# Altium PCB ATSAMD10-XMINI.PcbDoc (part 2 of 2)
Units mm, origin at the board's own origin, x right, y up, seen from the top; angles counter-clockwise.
Board outline 60 x 75 mm, 4 copper layers (Top Layer, GND, Power Plane, Bottom Layer), stack 1.578 mm thick; 62 components, 78 nets, 549 pads, 117 vias.
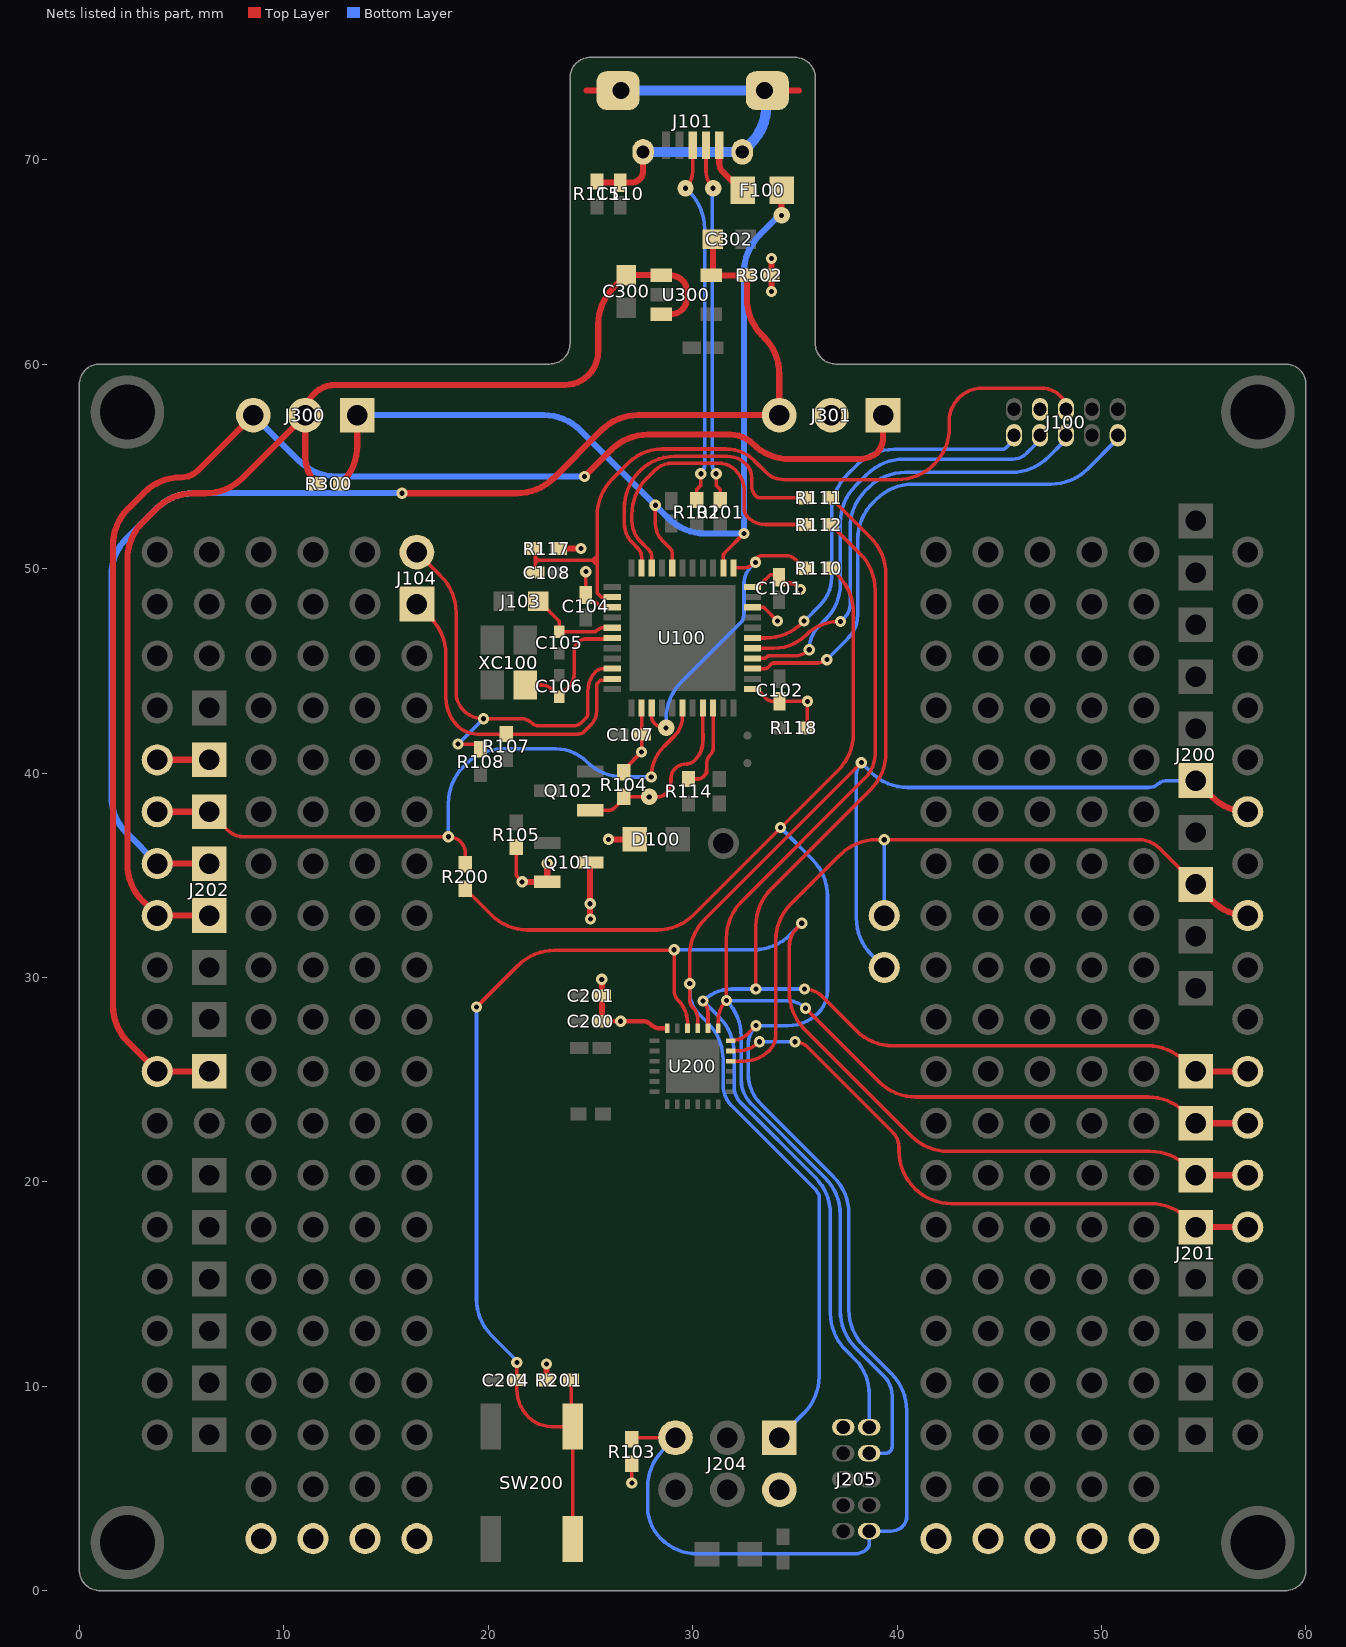
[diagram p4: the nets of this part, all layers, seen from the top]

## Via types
v1: diameter 0.55, hole 0.25, Top Layer to Bottom Layer, 102 vias
v2: diameter 0.55/0.55/0.8 (per signal layer), hole 0.25, Top Layer to Bottom Layer, tented top, 13 vias
v3: diameter 0.55, hole 0.25, Top Layer to Bottom Layer, tented top, 1 vias
v4: diameter 0.8, hole 0.4, Top Layer to Bottom Layer, 1 vias

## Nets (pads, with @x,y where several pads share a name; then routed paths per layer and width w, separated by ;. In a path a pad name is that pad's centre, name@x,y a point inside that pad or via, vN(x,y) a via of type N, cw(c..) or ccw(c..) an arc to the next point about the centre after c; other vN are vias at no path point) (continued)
PA23: J200.3@54.61,34.553 pad.12@57.15,33.029 pad.@39.37,33.029 U200.16 | length 38.1
  Top Layer w0.175: U200.16@31.86,25.909 32.487,25.909 ccw(c32.487,27.706) 33.757,26.435 ccw(c33.019,27.173) 34.063,27.173 34.063,31.806 cw(c36.603,31.806) 34.807,33.602 37.029,35.824 cw(c38.825,34.028) 37.239,36.013 cw(c38.997,34.256) 38.997,36.741 v1(39.37,36.741) 39.801,36.741 51.812,36.741 cw(c51.812,35.269) 52.853,36.31 J200.3@54.61,34.553
  Top Layer w0.3: J200.3@54.61,34.553 55.416,33.747 ccw(c57.15,35.481) pad.12@57.15,33.029
  Bottom Layer w0.175: pad.@39.37,33.029 v1(39.37,36.741)
PA24: J200.5@54.61,39.633 J204.1@34.24,7.489 pad.12@57.15,38.109 pad.@39.37,30.489 U200.21 | length 72.2
  Top Layer w0.175: U200.21@30.25,27.519 30.25,27.947 ccw(c29.391,27.947) 29.998,28.554 cw(c30.346,28.902) 29.854,28.902 v1(29.854,29.698) 29.854,31.061 cw(c32.394,31.061) 30.598,32.857 v1(38.25,40.509)
  Top Layer w0.3: J200.5@54.61,39.633 55.416,38.827 ccw(c57.15,40.561) pad.12@57.15,38.109
  Bottom Layer w0.175: v1(29.854,29.698) 29.854,29.3 ccw(c31.379,29.3) 30.301,28.222 30.742,27.781 cw(c28.946,25.985) 31.414,26.585 cw(c28.946,25.985) 31.486,25.985 31.486,24.741 ccw(c32.913,24.741) 31.904,23.732 35.975,19.66 cw(c35.349,19.034) 36.188,19.318 36.188,10.489 cw(c33.648,10.489) 35.444,8.693 J204.1@34.24,7.489 ; pad.@39.37,30.489 38.748,31.111 cw(c40.544,32.907) 38.004,32.907 38.004,39.914 cw(c38.845,39.914) v1(38.25,40.509) 38.719,40.039 ccw(c40.515,41.835) 40.515,39.295 52.288,39.295 ccw(c52.288,40.12) 52.658,39.383 cw(c53.267,38.764) 52.871,39.537 cw(c53.267,38.764) 53.267,39.633 J200.5@54.61,39.633
PA25: C204.2 J201.6@54.61,20.329 pad.12@57.15,20.329 R201.1 SW200.3 SW200.4 U200.22 | length 84.3
  Top Layer w0.175: v1(19.425,28.554) 21.459,30.587 cw(c23.255,28.791) 23.255,31.331 29.031,31.331 ccw(c29.031,31.418) v1(29.093,31.357) 29.093,29.352 ccw(c29.752,29.352) 29.286,28.886 cw(c28.166,27.766) 29.75,27.766 U200.22@29.75,27.519 ; v1(21.4,11.166) C204.2@21.4,10.309 21.4,9.857 ccw(c23.311,9.857) 21.96,8.506 ccw(c23.099,9.645) 23.099,8.034 SW200.4@24.125,8.034 ; SW200.4@23.795,8.975 23.795,8.829 ccw(c24.921,8.829) SW200.4@24.125,8.034 ; R201.1@24.05,10.309 24.05,8.215 ccw(c24.306,8.215) SW200.4@24.125,8.034 ; SW200.3@24.125,2.534 SW200.4@24.125,8.034 ; v1(35.336,32.655) 35.1,32.419 ccw(c36.004,31.515) 34.725,31.515 34.725,29.271 ccw(c37.265,29.271) 35.469,27.475 40.704,22.24 ccw(c42.5,24.036) 42.5,21.496 52.391,21.496 cw(c52.391,18.956) 54.187,20.752 J201.6@54.61,20.329 cw(c54.61,20.93) 54.185,20.505 J201.6@53.938,20.752
  Top Layer w0.3: J201.6@54.61,20.329 pad.12@57.15,20.329
  Bottom Layer w0.175: v1(19.425,28.554) 19.425,14.277 ccw(c21.965,14.277) 20.169,12.481 21.424,11.225 cw(c21.341,11.225) v1(21.4,11.166) ; v1(29.093,31.357) 32.986,31.357 ccw(c32.986,33.897) 34.782,32.101 v1(35.336,32.655)
PA27: J201.5@54.61,17.789 pad.12@57.15,17.789 U200.17 | length 29.8
  Top Layer w0.175: U200.17@31.86,26.409 32.181,26.409 ccw(c32.181,27.943) 32.718,26.506 ccw(c32.181,27.943) v1(33.266,26.858) ; v1(35,26.859) cw(c35,26.005) 35.603,26.609 39.781,22.431 cw(c39.027,21.678) 40.093,21.678 40.093,21.506 ccw(c42.633,21.506) 40.837,19.71 40.867,19.68 ccw(c42.663,21.476) 42.663,18.936 52.41,18.936 cw(c52.41,16.396) 54.206,18.192 J201.5@54.61,17.789
  Top Layer w0.3: J201.5@54.61,17.789 pad.12@57.15,17.789
  Bottom Layer w0.175: v1(33.266,26.858) v1@35.049,26.858 ; v1(35,26.859) v1@35.049,26.859
PA28: J204.5@29.16,7.489 J205.10@38.635,2.919 R103.1 R110.2 R200.1 U200.18 | length 95.4
  Top Layer w0.175: R200.1@18.875,34.334 20.14,33.069 ccw(c21.936,34.865) 21.936,32.325 28.255,32.325 ccw(c28.255,34.865) 30.051,33.069 37.12,40.138 ccw(c35.324,41.934) 37.864,41.934 37.864,47.858 ccw(c35.324,47.858) 37.12,49.654 R110.2@36.758,50.016 ; R103.1@27.025,7.409 cw(c27.218,7.216) 27.218,7.489 J204.5@29.16,7.489 ; U200.18@31.86,26.909 ccw(c31.86,28.131) 32.725,27.267 v1(33.101,27.643)
  Bottom Layer w0.175: J204.5@29.16,7.489 28.539,6.868 ccw(c30.335,5.072) 27.795,5.072 27.795,4.101 ccw(c29.983,4.101) 28.436,2.554 ccw(c30.232,4.35) 30.232,1.81 37.925,1.81 ccw(c37.925,2.689) 38.547,2.068 ccw(c38.334,2.281) 38.635,2.281 J205.10@38.635,2.919 39.712,2.919 ccw(c39.712,3.704) 40.267,3.149 ccw(c39.78,3.636) 40.469,3.636 40.469,8.814 ccw(c37.929,8.814) 39.725,10.61 38.388,11.947 cw(c40.184,13.743) 37.644,13.743 37.644,18.443 ccw(c35.104,18.443) 36.9,20.239 33.325,23.814 cw(c34.791,25.28) 32.718,25.28 32.718,26.718 cw(c34.026,26.718) v1(33.101,27.643) 34.653,27.643 ccw(c34.653,29.738) 36.135,28.257 ccw(c35.027,29.365) 36.594,29.365 36.594,33.987 ccw(c34.054,33.987) 35.85,35.783 v1(34.295,37.338)
PA30: J201.7@54.61,22.869 J205.4@38.635,6.729 pad.12@57.15,22.869 R112.2 U200.19 | length 82.5
  Top Layer w0.175: U200.19@31.25,27.519 31.25,27.9 cw(c32.623,27.9) v1(31.652,28.871) 31.652,31.92 cw(c34.192,31.92) 32.396,33.716 38.444,39.765 ccw(c37.291,40.918) 38.922,40.918 38.922,48.942 ccw(c36.382,48.942) 38.178,50.739 R112.2@36.758,52.159 ; v1(35.516,28.498) 39.115,24.898 ccw(c40.911,26.694) 40.911,24.154 52.272,24.154 cw(c52.272,21.614) 54.068,23.41 J201.7@54.61,22.869
  Top Layer w0.3: J201.7@54.61,22.869 pad.12@57.15,22.869
  Bottom Layer w0.175: v1(35.516,28.498) ccw(c34.615,27.597) 34.615,28.871 v1(31.652,28.871) cw(c29.915,27.133) 32.372,27.133 32.372,25.03 ccw(c34.116,25.03) 32.883,23.797 36.476,20.203 cw(c34.68,18.407) 37.22,18.407 37.22,13.69 ccw(c39.76,13.69) 37.964,11.894 39.352,10.506 cw(c38.385,9.539) 39.753,9.539 39.753,7.044 cw(c39.438,7.044) 39.438,6.729 J205.4@38.635,6.729 ccw(c38.922,6.729) J205.4@38.922,6.441
PA31: J201.8@54.61,25.409 J205.2@38.635,7.999 pad.12@57.15,25.409 R111.2 U200.20 | length 80.7
  Top Layer w0.175: v1(30.51,28.852) cw(c29.932,28.273) 30.75,28.273 U200.20@30.75,27.519 ; v1(33.089,29.438) 33.089,32.522 cw(c35.629,32.522) 33.833,34.318 38.709,39.195 ccw(c36.913,40.991) 39.453,40.991 39.453,49.719 ccw(c36.913,49.719) 38.709,51.515 R111.2@36.758,53.466 ; v1(35.476,29.438) cw(c35.476,28.258) 36.31,29.093 37.997,27.405 ccw(c39.794,29.201) 39.794,26.661 52.248,26.661 cw(c52.248,24.121) 54.045,25.917 J201.8@54.553,25.409
  Top Layer w0.3: J201.8@54.61,25.409 pad.12@57.15,25.409
  Bottom Layer w0.175: v1(35.476,29.438) v1(33.089,29.438) 31.925,29.438 ccw(c31.925,27.437) v1(30.51,28.852) 31.284,28.078 cw(c29.488,26.282) 32.028,26.282 32.028,24.663 ccw(c33.167,24.663) 32.362,23.858 35.995,20.224 cw(c34.199,18.428) 36.739,18.428 36.739,13.574 ccw(c39.279,13.574) 37.27,12.021 ccw(c39.279,13.574) 37.483,11.778 38.105,11.157 cw(c36.095,9.604) 38.635,9.604 J205.2@38.635,7.999
PD2_UART_RXD1: J104.2@16.51,50.809 R108.1 U100.20 | length 21.1
  Top Layer w0.175: J104.2@16.51,50.809 17.681,49.638 cw(c15.885,47.842) 18.425,47.842 18.425,43.964 ccw(c19.705,43.964) 18.8,43.059 ccw(c19.766,44.024) v1(19.766,42.659) 21.607,42.659 cw(c21.607,41.89) 22.15,42.434 ccw(c22.452,42.735) 22.452,42.309 24.153,42.309 ccw(c24.153,42.906) 24.575,42.484 24.769,42.678 ccw(c24.513,42.934) 24.875,42.934 24.875,44.006 cw(c26.248,44.006) 25.277,44.977 cw(c25.595,44.66) 25.595,45.109 U100.20@26.075,45.109 ; v1(18.525,41.418) 19.366,41.418 R108.1@19.625,41.159
  Bottom Layer w0.175: v1(18.525,41.418) v1(19.766,42.659)
PD3_UART_TXD1: J104.1@16.51,48.269 R107.1 U100.21 | length 16.3
  Top Layer w0.175: J104.1@16.51,48.269 17.181,47.598 cw(c15.385,45.802) 17.925,45.802 17.925,43.697 ccw(c19.888,43.697) 18.5,42.309 ccw(c19.466,43.274) 19.466,41.909 R107.1@20.875,41.909 24.398,41.909 ccw(c24.398,42.335) 24.7,42.034 25.017,42.351 ; 25.017,42.351 ccw(c24.334,43.034) 25.3,43.034 25.3,44.26 cw(c25.533,44.26) 25.368,44.425 25.477,44.534 26,44.534 U100.21@26.075,44.609
POWER_ENABLE: Q102.1 R104.1 U100.30 | length 10.4
  Top Layer w0.175: Q102.1@24.985,38.179 25.902,38.179 ccw(c25.902,38.547) 25.962,38.184 ccw(c25.902,38.547) 26.162,38.286 26.565,38.69 ccw(c26.422,38.834) R104.1@26.625,38.834 v2(27.878,38.834) 28.306,38.834 ccw(c28.306,39.331) 28.658,38.979 ccw(c27.977,39.66) 28.94,39.66 28.94,39.764 cw(c29.566,39.764) 29.123,40.206 cw(c29.701,39.629) 29.701,40.445 ccw(c29.701,40.978) 30.077,40.601 ccw(c29.043,41.635) 30.178,40.713 ; U100.30@30.5,43.184 30.5,41.51 ; 30.505,41.919 30.505,41.635 cw(c29.043,41.635) 30.5,41.51 ; 30.178,40.713 ccw(c29.043,41.635) 30.5,41.51 ; 30.178,40.713 ccw(c29.4,41.491) 30.5,41.491 30.5,41.51
RESET_SENSE: J202.3@6.35,38.109 pad.0@3.81,38.109 R200.2 U100.28 | length 33.9
  Top Layer w0.175: J202.3@6.35,38.109 7.239,37.22 ccw(c8.05,38.03) 8.05,36.884 v1(18.046,36.884) cw(c18.046,36.03) 18.65,36.634 cw(c18.107,36.09) 18.875,36.09 R200.2@18.875,35.534 ; v1(27.975,39.809) cw(c30.087,39.809) 28.594,41.302 29.108,41.817 ccw(c28.163,42.762) U100.28@29.5,42.762 ; 29.5,42.736 U100.28@29.5,42.762 ; U100.28@29.5,43.184 U100.28@29.5,42.762
  Top Layer w0.3: pad.0@3.81,38.109 J202.3@6.35,38.109
  Bottom Layer w0.175: v1(18.046,36.884) 18.046,38.52 cw(c20.586,38.52) 18.79,40.316 18.957,40.482 cw(c20.656,38.784) 20.656,41.186 23.289,41.186 cw(c23.289,39.023) 24.819,40.553 ccw(c26.615,42.349) 26.615,39.809 v1(27.975,39.809)
S\R\S\T\: C108.2 J100.6@48.26,57.794 R117.1 U100.13 | length 38.3
  Top Layer w0.175: R117.1@22.25,50.984 cw(c22.129,50.863) 22.3,50.863 22.3,50.409 ; 22.298,50.262 22.3,50.264 ; C108.2@22.3,49.809 22.3,50.264 ; 22.306,50.562 22.459,50.409 ; 22.562,50.409 22.459,50.409 ; 25.2,50.409 25.097,50.409 ; U100.13@26.075,48.609 25.525,48.609 25.325,48.809 25.325,50.181 ; J100.6@48.26,57.794 ccw(c47.343,57.794) 47.991,58.442 ccw(c47.047,57.498) 47.047,58.834 44.175,58.834 ccw(c44.175,57.209) 42.631,57.714 ccw(c44.175,57.209) 42.559,57.383 42.559,56.906 cw(c40.019,56.906) 41.815,55.11 41.802,55.097 cw(c40.006,56.893) 40.006,54.353 34.464,54.353 cw(c34.464,55.618) 33.569,54.723 33.002,55.291 ccw(c31.65,53.939) 31.65,55.851 28.499,55.851 ccw(c28.499,53.525) 26.854,55.17 26.069,54.384 ccw(c27.865,52.588) 25.325,52.588 25.325,50.637 ; 22.3,50.264 22.444,50.409 ; 22.3,50.264 22.3,50.409 ; 22.3,50.409 22.444,50.409 ; 22.444,50.409 22.459,50.409 ; 22.459,50.409 25.097,50.409 ; 25.097,50.409 25.325,50.637 ; 25.097,50.409 25.325,50.181 ; 25.325,50.181 25.325,50.637
SHIELD: C110.2 J101.6@33.512,73.384 J101.7@26.488,73.384 J101.8@32.425,70.384 J101.9@27.575,70.384 R115.1 | length 23.8
  Top Layer w0.3: 24.819,73.384 J101.7@26.4,73.384 ; R115.1@25.315,68.935 ccw(c25.436,69.055) 25.436,68.885 C110.2@26.458,68.885 27.008,68.885 ccw(c27.008,69.454) 27.411,69.051 ccw(c27.015,69.448) 27.575,69.448 J101.9@27.575,70.384 ; J101.7@26.4,72.636 J101.7@26.4,73.384 ; J101.7@26.488,73.384 J101.7@26.4,73.384 ; J101.6@33.512,73.384 J101.6@33.6,73.384 ; J101.6@33.6,72.594 J101.6@33.6,73.384 ; 35.193,73.384 J101.6@33.6,73.384
  Bottom Layer w0.5: J101.7@26.4,73.384 J101.7@26.488,73.384 J101.6@33.512,73.384 33.6,73.384 33.6,72.611 cw(c31.06,72.611) 32.856,70.815 J101.8@32.425,70.384 J101.9@27.575,70.384
STATUS_LED: R114.2 U100.31 | length 4.6
  Top Layer w0.175: R114.2@29.8,39.709 30.26,39.709 ccw(c30.26,40.056) 30.505,39.81 30.683,39.988 30.683,40.437 cw(c31.377,40.437) 30.886,40.928 ccw(c30.612,41.202) 31,41.202 U100.31@31,43.184 ; 30.54,39.845 ccw(c30.193,40.191) 30.683,40.191
SWCLK: R112.1 U100.9 | length 15
  Top Layer w0.175: U100.9@28,50.034 28,50.535 ccw(c27.423,50.535) 27.831,50.943 27.446,51.328 cw(c28.467,52.349) 27.023,52.349 27.023,52.631 cw(c29.563,52.631) 27.767,54.427 28.141,54.801 cw(c29,53.943) 29,55.157 31.267,55.157 cw(c31.267,53.982) 32.097,54.813 cw(c31.06,53.775) 32.527,53.775 32.527,52.898 ccw(c33.049,52.898) 32.68,52.528 ccw(c33.573,53.421) 33.573,52.159 R112.1@35.558,52.159
SWDIO: R111.1 U100.10 | length 14.9
  Top Layer w0.175: U100.10@27.5,50.034 27.5,50.569 ccw(c26.907,50.569) 27.326,50.988 27.053,51.261 cw(c28.018,52.225) 26.654,52.225 26.654,52.96 cw(c29.194,52.96) 27.398,54.756 27.442,54.8 cw(c29.119,53.122) 29.119,55.494 31.68,55.494 cw(c31.68,54.174) 32.614,55.108 cw(c31.956,54.45) 32.886,54.45 32.886,54.054 ccw(c33.607,54.054) 32.915,53.85 ccw(c33.607,54.054) 33.097,53.544 ccw(c33.284,53.731) 33.284,53.466 R111.1@35.558,53.466
TARGET_RESET: R110.1 U100.1 U100.25 | length 15.4
  Top Layer w0.175: U100.25@28,43.184 28,42.735 ccw(c28.427,42.735) 28.125,42.434 ccw(c28.668,42.977) 28.668,42.209 v2(28.7,42.209) ; U100.1@32,50.034 32.434,50.034 ccw(c32.434,50.947) v1@33.08,50.301 ; v1(33.075,50.309) cw(c33.4,50.309) 33.4,50.634 34.55,50.634 cw(c34.55,49.909) 35.275,49.909 R110.1@35.55,49.909
  Bottom Layer w0.175: v2(28.7,42.209) 28.7,42.657 cw(c31.24,42.657) 29.444,44.453 32.402,47.411 ; 32.402,47.411 ccw(c32.283,47.53) 32.452,47.53 ccw(c31.793,47.819) 32.512,47.819 32.512,49.285 cw(c33.625,49.285) 32.838,50.072 v1(33.075,50.309)
TCK: J100.1@45.72,56.524 U100.39 | length 19.5
  Top Layer w0.175: U100.39@32.925,46.609 33.573,46.609 ccw(c33.573,49.149) 35.369,47.353 v1(35.45,47.434)
  Bottom Layer w0.175: v1(35.45,47.434) 36.234,48.218 ccw(c34.869,49.584) 36.8,49.584 36.8,52.782 cw(c39.34,52.782) 37.544,54.578 38.056,55.09 cw(c39.852,53.294) 39.852,55.834 45.15,55.834 ccw(c45.15,56.075) 45.321,55.904 45.564,56.148 ccw(c45.189,56.524) J100.1@45.72,56.524
TDI: J100.9@50.8,56.524 U100.36 | length 25.4
  Top Layer w0.175: U100.36@32.925,45.109 33.525,45.109 ccw(c33.525,45.35) 33.696,45.179 33.85,45.334 ; 33.85,45.334 cw(c33.971,45.213) 33.971,45.384 36.128,45.384 ccw(c36.128,45.981) 36.55,45.559 v1(36.562,45.547)
  Bottom Layer w0.175: v1(36.562,45.547) 37.581,46.565 ccw(c36.387,47.759) 38.075,47.759 38.075,51.432 cw(c40.615,51.432) 38.819,53.228 38.981,53.39 cw(c40.777,51.594) 40.777,54.134 47.523,54.134 ccw(c47.523,56.674) 49.319,54.878 50.683,56.242 ccw(c50.402,56.524) J100.9@50.8,56.524
TDO: J100.3@46.99,56.524 U100.37 | length 21.6
  Top Layer w0.175: U100.37@32.925,45.609 33.444,45.609 ccw(c33.444,45.865) 33.625,45.684 cw(c33.746,45.563) 33.746,45.734 34.976,45.734 ccw(c34.976,46.758) v1(35.7,46.034)
  Bottom Layer w0.175: v1(35.7,46.034) cw(c37.33,46.034) 36.177,47.186 36.5,47.509 ccw(c34.75,49.259) 36.6,47.615 ccw(c34.75,49.259) 37.225,49.259 37.225,52.257 cw(c39.765,52.257) 37.969,54.053 38.531,54.615 cw(c40.327,52.819) 40.327,55.359 45.65,55.359 ccw(c45.65,56.324) 46.333,55.641 46.831,56.14 ccw(c46.447,56.524) J100.3@46.99,56.524
TMS: J100.5@48.26,56.524 U100.38 | length 22.2
  Top Layer w0.175: U100.38@32.925,46.109 33.981,46.109 ccw(c33.981,48.328) 35.55,46.759 cw(c37.119,45.189) 37.119,47.409 v1(37.236,47.409)
  Bottom Layer w0.175: v1(37.236,47.409) 37.427,47.599 ccw(c36.767,48.259) 37.7,48.259 37.7,52.007 cw(c40.24,52.007) 38.444,53.803 38.606,53.965 cw(c40.402,52.169) 40.402,54.709 45.598,54.709 ccw(c45.598,57.249) 47.394,55.453 48.115,56.174 ccw(c47.765,56.524) J100.5@48.26,56.524
USB_VBUS: F100.1 J101.1 | length 2.7
  Top Layer w0.3: J101.1@31.3,70.709 31.3,69.831 ccw(c31.897,69.831) 31.475,69.409 32.322,68.562 ccw(c32.45,68.69) F100.1@32.45,68.509
USBD_N: J101.2 R101.1 | length 17.6
  Top Layer w0.18: J101.2@30.65,70.709 30.65,69.454 ccw(c31.845,69.454) v2(31,68.609) ; v1(31.15,54.644) 31.15,54.071 31.35,53.871 R101.1@31.35,53.359
  Bottom Layer w0.18: v2(31,68.609) ccw(c31.084,68.524) 30.965,68.524 30.965,55.091 ccw(c31.597,55.091) v1(31.15,54.644) v1@31.15,54.693
USBD_P: J101.3 R102.1 | length 17.9
  Top Layer w0.18: v2(29.65,68.609) ccw(c28.805,69.454) 30,69.454 J101.3@30,70.709 ; R102.1@30.2,53.359 30.2,53.871 30.4,54.071 v1(30.4,54.644)
  Bottom Layer w0.18: v2(29.65,68.609) 29.841,68.418 cw(c28.045,66.622) 30.585,66.622 30.585,55.091 cw(c29.953,55.091) v1(30.4,54.644)
VCC_BOARD: C101.2 C102.1 C104.1 C107.2 D100.2 J100.4@46.99,57.794 J301.2@36.775,57.509 Q101.2 R104.2 R105.2 R117.2 R118.2 R302.2 U100.14 U100.24 U100.34 U100.42 U100.44 | length 22.6
  Top Layer w0.175: R105.2@21.375,36.384 21.375,35.054 ccw(c21.546,35.054) 21.425,34.934 21.644,34.715 cw(c21.607,34.679) v1(21.659,34.679) ; v1(24.775,49.853) C104.1@24.775,48.709 24.775,48.578 24.819,48.534 ccw(c24.819,48.665) 24.912,48.572 cw(c24.698,48.359) 25,48.359 25.275,48.359 25.525,48.109 U100.14@26.075,48.109 ; R104.2@26.625,40.034 cw(c26.916,40.034) 26.71,40.24 v1(27.5,41.029) C107.2@27.5,41.884 U100.24@27.5,43.184 ; U100.34@32.925,44.109 cw(c32.925,43.626) 33.266,43.967 33.575,43.659 ccw(c33.937,44.021) 33.937,43.509 C102.1@34.25,43.509 v1(35.615,43.509) 35.615,42.365 cw(c35.394,42.365) R118.2@35.55,42.209 ; U100.42@32.925,48.109 33.44,48.109 cw(c33.44,48.023) 33.5,48.084 v1(34.15,47.434) ; U100.44@32.925,49.109 ccw(c32.925,49.773) 33.394,49.303 33.8,49.709 C101.2@34.225,49.709
  Top Layer w0.2: 34.525,49.284 34.95,49.284 35.25,48.984 v1(35.275,48.984)
  Top Layer w0.3: v1(21.659,34.679) Q101.2@22.885,34.679 v1(22.885,35.572) ; R117.2@23.45,50.984 v1(24.54,50.984) ; v1(25.885,36.759) D100.2@27.175,36.759 ; v1(33.851,63.558) R302.2@33.851,64.357 v1(33.851,65.176)
  Bottom Layer w0.3: v1@21.55,34.634 cw(c21.659,34.525) v1(21.659,34.679) ; v1(22.885,35.572) cw(c22.936,35.572) v1@22.9,35.609
VCC_P3V3: C302.1 J202.4@6.35,35.569 J301.3@34.235,57.509 pad.0@3.81,35.569 R302.1 U300.5 | length 64.4
  Top Layer w0.3: pad.0@3.81,35.569 J202.4@6.35,35.569 ; v1(15.775,53.689) 21.404,53.689 ccw(c21.404,56.229) 23.2,54.433 25.532,56.765 cw(c27.328,54.969) 27.328,57.509 J301.3@34.235,57.509 34.235,59.528 ccw(c31.695,59.528) 33.491,61.325 33.395,61.42 cw(c35.191,63.217) 32.651,63.217 R302.1@32.651,64.357 cw(c32.623,64.385) 32.623,64.345 U300.5@30.918,64.345 ccw(c30.753,64.51) 30.986,64.51 C302.1@30.986,66.12
  Bottom Layer w0.3: pad.0@3.81,35.569 2.308,37.071 cw(c4.104,38.867) 1.564,38.867 1.564,49.683 cw(c4.104,49.683) 2.308,51.479 3.781,52.952 cw(c5.577,51.156) 5.577,53.696 v1@15.775,53.696
VCC_P5V0: C300.1 J202.5@6.35,33.029 J300.2@11.05,57.509 pad.0@3.81,33.029 R300.2 U300.1 U300.3 | length 61.6
  Top Layer w0.3: J202.5@6.35,33.029 pad.0@3.81,33.029 3.094,33.745 cw(c4.89,35.541) 2.35,35.541 2.35,50.468 cw(c4.89,50.468) 3.094,52.265 3.771,52.941 cw(c5.567,51.145) 5.567,53.685 6.174,53.685 ccw(c6.174,56.225) 7.97,54.429 J300.2@11.05,57.509 ; R300.2@11.6,54.159 cw(c12.928,55.486) 11.05,55.486 J300.2@11.05,57.509 ; U300.3@28.468,62.439 28.901,62.439 ccw(c28.901,63.298) 29.508,62.691 ccw(c29.062,63.137) 29.693,63.137 29.693,63.648 ccw(c29.062,63.648) 29.508,64.094 ccw(c28.901,63.487) 28.901,64.345 U300.1@28.468,64.345 ccw(c28.43,64.308) 28.43,64.361 C300.1@26.747,64.361 26.122,63.736 ccw(c27.918,61.94) 25.378,61.94 25.378,60.629 cw(c23.726,60.629) 24.894,59.461 cw(c23.754,60.602) 23.754,58.989 12.53,58.989 ccw(c12.53,57.509) J300.2@11.05,57.509
VCC_TARGET: C200.2 C201.2 J202.2@6.35,40.649 J204.2@34.24,4.949 J205.1@37.365,7.999 pad.0@3.81,40.649 pad.2@8.89,2.549 pad.3@11.43,2.549 pad.4@13.97,2.549 pad.5@16.51,2.549 pad.6@41.91,2.549 pad.7@44.45,2.549 pad.8@46.99,2.549 pad.9@49.53,2.549 pad.10@52.07,2.549 Q101.3 R103.2 R201.2 U200.24 | length 13.6
  Top Layer w0.175: v1(27.025,5.277) R103.2@27.025,6.209
  Top Layer w0.22: C200.2@25.566,27.861 v1(26.476,27.861) 27.578,27.861 cw(c27.578,27.344) 27.943,27.71 ccw(c28.405,28.171) 28.405,27.519 U200.24@28.75,27.519
  Top Layer w0.3: pad.0@3.81,40.649 J202.2@6.35,40.649 J202.2@5.669,39.967 ; R201.2@22.85,10.309 v1(22.85,11.099) ; Q101.3@24.985,35.629 v1(24.985,33.609) 24.985,32.874 v1(25,32.859) ; v1(25.55,29.909) 25.55,30.005 25.566,30.021 C201.2@25.566,29.111 C200.2@25.566,27.861
VCC_VBUS: F100.2 J300.1@13.59,57.509 R300.1 U100.2 U100.7 | length 47.6
  Top Layer w0.175: v1(28.175,53.101) 28.175,52.209 ccw(c29.382,52.209) 28.528,51.355 28.9,50.984 cw(c28.659,50.742) 29,50.742 U100.7@29,50.034 ; U100.2@31.5,50.034 31.5,50.638 cw(c31.671,50.638) 31.55,50.758 ; 31.55,50.759 v1(32.512,51.72)
  Top Layer w0.3: R300.1@12.8,54.159 12.846,54.205 ccw(c11.05,56.001) 13.59,56.001 J300.1@13.59,57.509 ; v2(34.35,67.284) F100.2@34.35,68.509
  Bottom Layer w0.3: J300.1@13.59,57.509 22.715,57.509 cw(c22.715,54.969) 24.511,56.765 v1(28.175,53.101) 28.812,52.464 ccw(c30.608,54.26) 30.608,51.72 v1(32.512,51.72) 32.512,64.502 cw(c35.052,64.502) 33.256,66.298 34.241,67.284 v2(34.35,67.284)
VCC_VIN: J202.8@6.35,25.409 J300.3@8.51,57.509 J301.1@39.315,57.509 pad.0@3.81,25.409 | length 73.6
  Top Layer w0.3: J202.8@6.35,25.409 pad.0@3.81,25.409 2.387,26.832 cw(c4.183,28.628) 1.643,28.628 1.643,51.145 cw(c4.183,51.145) 2.387,52.941 3.165,53.719 cw(c4.961,51.923) 4.961,54.463 ccw(c4.961,55.678) 5.82,54.819 J300.3@8.51,57.509 ; v1(24.714,54.512) 26.014,55.811 cw(c27.81,54.015) 27.81,56.555 31.852,56.555 cw(c31.852,55.006) 32.948,56.102 ccw(c34.744,57.898) 34.744,55.358 38.115,55.358 ccw(c38.115,56.868) 38.989,55.637 ccw(c38.204,56.423) 39.315,56.423 J301.1@39.315,57.509
  Bottom Layer w0.3: J300.3@8.51,57.509 10.763,55.255 ccw(c12.559,57.052) 12.559,54.512 v1(24.714,54.512)
XTAL1: C106.1 U100.17 XC100.1 | length 6.5
  Top Layer w0.175: XC100.1@21.9,44.309 22.598,44.309 cw(c22.598,43.58) 23.113,44.095 C106.1@23.475,43.734 23.923,44.181 ccw(c23.243,44.862) 23.928,44.186 ccw(c23.243,44.862) 24.205,44.862 24.205,46.043 cw(c24.616,46.043) 24.325,46.334 24.409,46.417 cw(c24.75,46.076) 24.75,46.559 25.954,46.559 ccw(c25.954,46.729) U100.17@26.075,46.609
XTAL2: C105.2 J103.2 U100.16 | length 4.6
  Top Layer w0.175: J103.2@22.45,48.409 cw(c22.45,48.288) 22.535,48.373 23.475,47.434 C105.2@23.475,46.909 25.144,46.909 ccw(c25.144,47.165) 25.325,46.984 cw(c25.627,46.682) 25.627,47.109 U100.16@26.075,47.109
pads on no net: J100.1@45.72,56.524 J100.2@45.72,57.794 J100.3@46.99,56.524 J100.4@46.99,57.794 J100.5@48.26,56.524 J100.6@48.26,57.794 J100.7@49.53,56.524 J100.8@49.53,57.794 J100.9@50.8,56.524 J100.10@50.8,57.794 J101.6@33.6,73.384 J101.7@26.4,73.384 J101.8@32.425,70.384 J101.9@27.575,70.384 J104.1@16.51,48.269 J104.2@16.51,50.809 J200.1@54.61,29.473 J200.2@54.61,32.013 J200.3@54.61,34.553 J200.4@54.61,37.093 J200.5@54.61,39.633 J200.6@54.61,42.173 J200.7@54.61,44.713 J200.8@54.61,47.253 J200.9@54.61,49.793 J200.10@54.61,52.333 J201.1@54.61,7.629 J201.2@54.61,10.169 J201.3@54.61,12.709 J201.4@54.61,15.249 J201.5@54.61,17.789 J201.6@54.61,20.329 J201.7@54.61,22.869 J201.8@54.61,25.409 J202.1@6.35,43.189 J202.2@6.35,40.649 J202.3@6.35,38.109 J202.4@6.35,35.569 J202.5@6.35,33.029 J202.6@6.35,30.489 J202.7@6.35,27.949 J202.8@6.35,25.409 J203.1@6.35,20.329 J203.2@6.35,17.789 J203.3@6.35,15.249 J203.4@6.35,12.709 J203.5@6.35,10.169 J203.6@6.35,7.629 J204.1@34.24,7.489 J204.2@34.24,4.949 J204.3@31.7,7.489 J204.4@31.7,4.949 J204.5@29.16,7.489 J204.6@29.16,4.949 J205.1@37.365,7.999 J205.2@38.635,7.999 J205.3@37.365,6.729 J205.4@38.635,6.729 J205.5@37.365,5.459 J205.6@38.635,5.459 J205.7@37.365,4.189 J205.8@38.635,4.189 J205.9@37.365,2.919 J205.10@38.635,2.919 J300.1@13.59,57.509 J300.2@11.05,57.509 J300.3@8.51,57.509 J301.1@39.315,57.509 J301.2@36.775,57.509 J301.3@34.235,57.509 QT200.1 U200.0
copper on no net: | length 238.8
  Top Layer w0.3: 3.81,22.869 6.35,22.869 ; 3.81,45.729 6.35,45.729 ; 3.81,48.269 6.35,48.269 ; 3.81,50.809 6.35,50.809 ; 8.89,7.629 11.43,7.629 ; 8.89,10.169 11.43,10.169 ; 8.89,12.709 11.43,12.709 ; 8.89,15.249 11.43,15.249 ; 8.89,17.789 11.43,17.789 ; 8.89,20.329 11.43,20.329 ; 8.89,22.869 11.43,22.869 ; 8.89,25.409 11.43,25.409 ; 8.89,27.949 11.43,27.949 ; 8.89,30.489 11.43,30.489 ; 8.89,33.029 11.43,33.029 ; 8.89,35.569 11.43,35.569 ; 8.89,38.109 11.43,38.109 ; 8.89,45.729 11.43,45.729 ; 8.89,48.269 11.43,48.269 13.97,48.269 ; 8.89,50.809 11.43,50.809 13.97,50.809 ; 13.97,7.629 16.51,7.629 ; 13.97,10.169 16.51,10.169 ; 13.97,12.709 16.51,12.709 ; 13.97,15.249 16.51,15.249 ; 13.97,17.789 16.51,17.789 ; 13.97,20.329 16.51,20.329 ; 13.97,22.869 16.51,22.869 ; 13.97,25.409 16.51,25.409 ; 13.97,27.949 16.51,27.949 ; 13.97,30.489 16.51,30.489 ; 13.97,33.029 16.51,33.029 ; 13.97,35.569 16.51,35.569 ; 13.97,38.109 16.51,38.109 ; 13.97,40.649 16.51,40.649 ; 13.97,43.189 16.51,43.189 ; 13.97,45.729 16.51,45.729 ; 41.91,7.629 44.45,7.629 ; 41.91,10.169 44.45,10.169 ; 41.91,12.709 44.45,12.709 ; 41.91,15.249 44.45,15.249 ; 41.91,17.789 44.45,17.789 ; 41.91,20.329 44.45,20.329 ; 41.91,22.869 44.45,22.869 ; 41.91,25.409 44.45,25.409 ; 41.91,27.949 44.45,27.949 ; 41.91,30.489 44.45,30.489 ; 41.91,33.029 44.45,33.029 ; 41.91,35.569 44.45,35.569 ; 41.91,38.109 44.45,38.109 ; 41.91,40.649 44.45,40.649 ; 41.91,43.189 44.45,43.189 ; 41.91,45.729 44.45,45.729 ; 41.91,48.269 44.45,48.269 ; 41.91,50.809 44.45,50.809 ; 46.99,7.629 52.07,7.629 ; 46.99,10.169 52.07,10.169 ; 46.99,12.709 52.07,12.709 ; 46.99,15.249 52.07,15.249 ; 46.99,17.789 52.07,17.789 ; 46.99,20.329 52.07,20.329 ; 46.99,22.869 52.07,22.869 ; 46.99,25.409 52.07,25.409 ; 46.99,27.949 52.07,27.949 ; 46.99,30.489 49.53,30.489 ; 46.99,33.029 49.53,33.029 ; 46.99,35.569 52.07,35.569 ; 46.99,38.109 52.07,38.109 ; 46.99,40.649 52.07,40.649 ; 46.99,43.189 52.07,43.189 ; 46.99,45.729 52.07,45.729 ; 46.99,48.269 52.07,48.269 ; 46.99,50.809 52.07,50.809 ; 8.89,40.649 11.43,40.649 8.89,40.649 ; 8.89,43.189 11.43,43.189 8.89,43.189

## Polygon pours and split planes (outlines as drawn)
no net on Top Overlay "GND Silk" (solid, pour order 16): 56,0.209 59.2,0.209 ccw(c59.2,0.709) 59.7,0.709 59.7,3.909 ccw(c59.2,3.909) 59.2,4.409 56,4.409 ccw(c56,3.909) 55.5,3.909 55.5,0.709 ccw(c56,0.709) 56,0.209
GND on Top Layer "Top-GND" (solid, remove dead copper, pour order 13): 0,0.009 0,69.207 60,69.207 60,0.009
SHIELD on Top Layer "USB Shield" (solid, remove dead copper, pour order 10): 25.25,69.709 24.92,69.709 cw(c24.92,70.38) 24.249,70.38 24.249,73.757 cw(c25.25,73.757) 25.25,74.759 34.75,74.759 cw(c34.75,73.759) 35.75,73.759 35.75,70.709 cw(c34.75,70.709) 34.75,69.709
GND on Bottom Layer "Bot-GND" (solid, remove dead copper, pour order 12): 0,0.009 0,69.207 60,69.207 60,0.009
SHIELD on GND "USB Shield" (solid, remove dead copper, pour order 9): 25.25,69.709 24.92,69.709 cw(c24.92,70.38) 24.249,70.38 24.249,73.757 cw(c25.25,73.757) 25.25,74.759 34.75,74.759 cw(c34.75,73.759) 35.75,73.759 35.75,70.709 cw(c34.75,70.709) 34.75,69.709
GND on GND "L2-GND" (solid, remove dead copper, pour order 11): 0,0.009 0,69.207 60,69.207 60,0.009
NetQT200_1 on GND "Touch" (solid, remove dead copper, pour order 8): 26.028,19.325 34.028,19.325 34.028,11.325 26.028,11.325
VCC_BOARD on Power Plane (split plane): 35.096,74.491 35.188,74.463 35.273,74.418 35.348,74.356 35.409,74.282 35.454,74.197 35.482,74.105 35.491,74.02 35.49,74.009 35.49,61.009 35.49,61.007 35.499,60.84 35.527,60.673 35.574,60.51 35.639,60.353 35.721,60.205 35.819,60.067 35.932,59.941 36.058,59.828 36.196,59.73 36.345,59.648 36.501,59.583 36.664,59.536 36.831,59.508 36.998,59.498 37,59.498 59,59.498 59.012,59.499 59.096,59.491 59.188,59.463 59.273,59.418 59.348,59.356 59.409,59.282 59.454,59.197 59.482,59.105 59.491,59.02 59.49,59.009 59.49,34.272 20.637,34.272 10.242,44.667 10.21,44.691 10.195,44.698 10.174,44.706 10.135,44.712 0.51,44.712 0.51,59.009 0.509,59.02 0.518,59.105 0.546,59.197 0.591,59.282 0.652,59.356 0.727,59.418 0.812,59.463 0.904,59.491 0.988,59.499 1,59.498 23,59.498 23.002,59.498 23.169,59.508 23.336,59.536 23.499,59.583 23.655,59.648 23.804,59.73 23.942,59.828 24.068,59.941 24.181,60.067 24.279,60.205 24.361,60.353 24.426,60.51 24.473,60.673 24.501,60.84 24.51,61.007 24.51,61.009 24.51,74.009 24.509,74.02 24.518,74.105 24.546,74.197 24.591,74.282 24.652,74.356 24.727,74.418 24.812,74.463 24.904,74.491 24.988,74.499 25,74.498 35,74.498 35.012,74.499
VCC_TARGET on Power Plane (split plane): 20.467,34.014 20.498,33.99 20.513,33.984 20.535,33.975 20.574,33.97 59.49,33.97 59.49,1.009 59.491,0.997 59.482,0.913 59.454,0.82 59.409,0.735 59.348,0.661 59.273,0.6 59.188,0.554 59.096,0.526 59.012,0.518 59,0.519 1,0.519 0.988,0.518 0.904,0.526 0.812,0.554 0.727,0.6 0.652,0.661 0.591,0.735 0.546,0.82 0.518,0.913 0.509,0.997 0.51,1.009 0.51,44.409 10.072,44.409

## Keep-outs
Keep-Out Layer:
  lines w0.1: 0.3,1.309 ccw(c1.3,1.309) 1.3,0.309 58.7,0.309 ccw(c58.7,1.309) 59.7,1.309 59.7,58.759 ccw(c58.7,58.759) 58.7,59.759 36.75,59.759 cw(c36.75,60.759) 35.75,60.759 35.75,73.759 ccw(c34.75,73.759) 34.75,74.759 25.25,74.759 ccw(c25.25,73.759) 24.25,73.759 24.25,60.759 cw(c23.25,60.759) 23.25,59.759 1.3,59.759 ccw(c1.3,58.759) 0.3,58.759 0.3,1.309

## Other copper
Top Layer:
  pour cut-out: 24.028,9.325 36.028,9.325 36.028,21.325 24.028,21.325
  pour cut-out: 31.693,65.142 31.693,61.642 27.674,61.642 27.674,65.146
  pour cut-out: 20,47.684 23.2,47.684 23.2,49.134 20,49.134
GND:
  pour cut-out: 26.028,19.325 34.028,19.325 34.028,11.325 36.028,11.325 36.028,21.325 24.028,21.325 24.028,9.325 36.028,9.325 36.028,11.325 26.028,11.325
Bottom Layer:
  pour cut-out: 24.028,9.325 36.028,9.325 36.028,21.325 24.028,21.325
Power Plane (plane layer: these items are gaps in the copper):
  rectangle: 24.028,9.325 36.028,21.325
  lines w0.3: 0,44.56 10.135,44.56 20.574,34.121 59.817,34.121

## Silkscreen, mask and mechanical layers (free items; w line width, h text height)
Top Overlay:
  drawing of 177 lines, arcs and shapes, not listed
  text "VIN" at 7.85,59.159 h1.1
  text "VBUS" at 12.4,59.159 h1.1
  text "3V3" at 33.401,59.159 h1.1
  text "VIN" at 38.35,59.159 h1.1
  text "11" at 53.9,54.909 h1.52
  text "GND" at 56.185,54.796 h1.52
  text "GND" at 0.914,54.669 h1.52
  text "X" at 28.718,54.578 h4
  text "PLAINED" at 32.159,54.578 h2
  text "MINI" at 41.225,54.578 h1
  text "SAMD10" at 19.886,54.095 h2
  text "0" at 3.5,52.409 h1.52
  text "1" at 6.04,52.409 h1.52
  text "2" at 8.58,52.409 h1.52
  text "3" at 11.12,52.409 h1.52
  text "4" at 13.66,52.409 h1.52
  text "5" at 16.2,52.409 h1.52
  text "6" at 41.6,52.409 h1.52
  text "7" at 44.14,52.409 h1.52
  text "8" at 46.68,52.409 h1.52
  text "9" at 49.22,52.409 h1.52
  text "10" at 51.26,52.409 h1.52
  text "12" at 56.34,52.409 h1.52
  text "mEDBG" at 24.2,51.009 h1.3
  text "R" at 40.54,50.409 h1.52 r90
  text "RX" at 18.376,50.351 h1.52
  text "PA15" at 59.05,49.865 h1.1 r90
  text "Q" at 40.54,47.869 h1.52 r90
  text "TX" at 18.2,47.709 h1.52
  text "PA14" at 59.05,47.101 h1.1 r90
  text "P" at 18.6,45.469 h1.52 r90
  text "P" at 40.54,45.329 h1.52 r90
  text "AREF" at 59.05,44.323 h1.1 r90
  text "NC" at 2.169,43.026 h1.3 r90
  text "O" at 18.6,42.929 h1.52 r90
  text "O" at 40.54,42.789 h1.52 r90
  text "GND" at 59.05,42.173 h1.1 r90
  text "BOOT" at 28.45,41.109 h1.4
  text "N" at 18.6,40.389 h1.52 r90
  text "N" at 40.54,40.249 h1.52 r90
  text "VCC" at 2.169,39.979 h1.3 r90
  text "PA09" at 59.05,39.723 h1.1 r90
  text "M" at 18.6,37.849 h1.52 r90
  text "M" at 40.54,37.709 h1.52 r90
  text "RST" at 2.169,37.483 h1.3 r90
  text "PA24" at 59.05,37.073 h1.1 r90
  text "EXT_CLK" at 32.715,36.105 h1.52
  text "L" at 40.54,35.169 h1.52 r90
  text "3V3" at 2.169,34.796 h1.3 r90
  text "PA22" at 59.05,34.423 h1.1 r90
  text "K" at 18.6,32.769 h1.52 r90
  text "5V" at 2.169,32.626 h1.3 r90
  text "PA23" at 59.05,31.823 h1.1 r90
  text "J" at 18.6,30.198 h1.52 r90
  text "B" at 22.258,29.822 h10
  text "GND" at 2.169,29.691 h1.3 r90
  text "NC" at 59.05,29.677 h1.1 r90
  text "I" at 18.6,27.683 h1.52 r90
  text "I" at 40.54,27.549 h1.52 r90
  text "NC" at 59.05,27.173 h1.1 r90
  text "GND" at 2.169,26.847 h1.3 r90
  text "H" at 18.6,25.136 h1.52 r90
  text "H" at 40.54,25.009 h1.52 r90
  text "VIN" at 2.169,24.576 h1.3 r90
  text "PA31" at 59.05,24.523 h1.1 r90
  text "G" at 18.6,22.609 h1.52 r90
  text "G" at 40.54,22.469 h1.52 r90
  text "PA30" at 59.05,21.923 h1.1 r90
  text "SAMD10" at 27.343,21.842 h1.52
  text "F" at 18.6,20.069 h1.52 r90
  text "F" at 40.54,19.929 h1.52 r90
  text "PA2" at 2.169,19.629 h1.3 r90
  text "PA25" at 59.05,19.323 h1.1 r90
  text "E" at 18.6,17.529 h1.52 r90
  text "E" at 40.54,17.389 h1.52 r90
  text "PA3" at 2.169,16.987 h1.3 r90
  text "PA27" at 59.05,16.773 h1.1 r90
  text "D" at 18.6,14.989 h1.52 r90
  text "D" at 40.54,14.849 h1.52 r90
  text "PA4" at 2.169,14.367 h1.3 r90
  text "PA17" at 59.05,14.273 h1.1 r90
  text "C" at 18.6,12.449 h1.52 r90
  text "C" at 40.54,12.309 h1.52 r90
  text "PA5" at 2.169,11.826 h1.3 r90
  text "PA16" at 59.05,11.623 h1.1 r90
  text "B" at 18.6,9.909 h1.52 r90
  text "B" at 40.8,9.809 h1.52 r90
  text "SWD" at 36.5,9.409 h1.52
  text "PA6" at 2.169,9.274 h1.3 r90
  text "SPI" at 30.734,9.127 h1.52
  text "PA10" at 59.05,9.073 h1.1 r90
  text "A" at 18.6,7.369 h1.52 r90
  text "A" at 41,7.209 h1.3 r90
  text "PA11" at 59.05,6.659 h1.1 r90
  text "PA7" at 2.169,6.621 h1.3 r90
  text "GND" at 56.362,4.797 h1.52
  text "GND" at 0.85,4.534 h1.52
  text "GND" at 4.525,4.484 h1.52
  text "GND" at 53.399,4.41 h1.52
  text "VCC" at 4.65,2.034 h1.52
  text "SW0" at 25.603,0.999 h1.52
  text "VCC" at 54.727,0.891 h1.52 r90
  text "LED0" at 35.2,0.759 h1.52
Bottom Overlay:
  lines w0.2: 30.014,42.186 30.497,41.703 39.085,41.703 39.085,52.326 30.014,52.326 30.014,42.186
  lines w0.4: 4.826,7.629 5.232,7.629 ; 4.826,10.169 5.232,10.169 ; 4.826,12.709 5.232,12.709 ; 4.826,15.249 5.232,15.249 ; 4.826,17.789 5.232,17.789 ; 4.826,20.329 5.232,20.329 ; 4.826,22.869 5.334,22.869 ; 4.826,25.409 5.232,25.409 ; 4.826,27.949 5.232,27.949 ; 4.826,30.489 5.232,30.489 ; 4.826,33.029 5.232,33.029 ; 4.826,35.569 5.232,35.569 ; 4.826,38.109 5.232,38.109 ; 4.826,40.649 5.232,40.649 ; 4.826,43.189 5.232,43.189 ; 4.826,45.729 5.334,45.729 ; 4.826,48.269 5.334,48.269 ; 4.826,50.809 5.334,50.809 ; 9.906,2.549 10.414,2.549 ; 9.906,5.089 10.414,5.089 ; 9.906,7.629 10.414,7.629 ; 9.906,10.169 10.414,10.169 ; 9.906,12.709 10.414,12.709 ; 9.906,15.249 10.414,15.249 ; 9.906,17.789 10.414,17.789 ; 9.906,20.329 10.414,20.329 ; 9.906,22.869 10.414,22.869 ; 9.906,25.409 10.414,25.409 ; 9.906,27.949 10.414,27.949 ; 9.906,30.489 10.414,30.489 ; 9.906,33.029 10.414,33.029 ; 9.906,35.569 10.414,35.569 ; 9.906,38.109 10.414,38.109 ; 9.906,40.649 10.414,40.649 ; 9.906,43.189 10.414,43.189 ; 9.906,45.729 10.414,45.729 ; 9.906,48.269 10.414,48.269 ; 9.906,50.809 10.414,50.809 ; 12.446,2.549 12.954,2.549 ; 12.446,5.089 12.954,5.089 ; 12.446,48.269 12.954,48.269 ; 12.446,50.809 12.954,50.809 ; 14.986,2.549 15.494,2.549 ; 14.986,5.089 15.494,5.089 ; 14.986,7.629 15.494,7.629 ; 14.986,10.169 15.494,10.169 ; 14.986,12.709 15.494,12.709 ; 14.986,15.249 15.494,15.249 ; 14.986,17.789 15.494,17.789 ; 14.986,20.329 15.494,20.329 ; 14.986,22.869 15.494,22.869 ; 14.986,25.409 15.494,25.409 ; 14.986,27.949 15.494,27.949 ; 14.986,30.489 15.494,30.489 ; 14.986,33.029 15.494,33.029 ; 14.986,35.569 15.494,35.569 ; 14.986,38.109 15.494,38.109 ; 14.986,40.649 15.494,40.649 ; 14.986,43.189 15.494,43.189 ; 14.986,45.729 15.494,45.729 ; 42.926,2.549 43.434,2.549 ; 42.926,5.089 43.434,5.089 ; 42.926,7.629 43.434,7.629 ; 42.926,10.169 43.434,10.169 ; 42.926,12.709 43.434,12.709 ; 42.926,15.249 43.434,15.249 ; 42.926,17.789 43.434,17.789 ; 42.926,20.329 43.434,20.329 ; 42.926,22.869 43.434,22.869 ; 42.926,25.409 43.434,25.409 ; 42.926,27.949 43.434,27.949 ; 42.926,30.489 43.434,30.489 ; 42.926,33.029 43.434,33.029 ; 42.926,35.569 43.434,35.569 ; 42.926,38.109 43.434,38.109 ; 42.926,40.649 43.434,40.649 ; 42.926,43.189 43.434,43.189 ; 42.926,45.729 43.434,45.729 ; 42.926,48.269 43.434,48.269 ; 42.926,50.809 43.434,50.809 ; 45.466,2.549 45.974,2.549 ; 45.466,5.089 45.974,5.089 ; 48.006,2.549 48.514,2.549 ; 48.006,5.089 48.514,5.089 ; 48.006,7.629 48.514,7.629 ; 48.006,10.169 48.514,10.169 ; 48.006,12.709 48.514,12.709 ; 48.006,15.249 48.514,15.249 ; 48.006,17.789 48.514,17.789 ; 48.006,20.329 48.514,20.329 ; 48.006,22.869 48.514,22.869 ; 48.006,25.409 48.514,25.409 ; 48.006,27.949 48.514,27.949 ; 48.006,30.489 48.514,30.489 ; 48.006,33.029 48.514,33.029 ; 48.006,35.569 48.514,35.569 ; 48.006,38.109 48.514,38.109 ; 48.006,40.649 48.514,40.649 ; 48.006,43.189 48.514,43.189 ; 48.006,45.729 48.514,45.729 ; 48.006,48.269 48.514,48.269 ; 48.006,50.809 48.514,50.809 ; 50.546,2.549 51.054,2.549 ; 50.546,5.089 51.054,5.089 ; 50.546,7.629 51.054,7.629 ; 50.546,10.169 51.054,10.169 ; 50.546,12.709 51.054,12.709 ; 50.546,15.249 51.054,15.249 ; 50.546,17.789 51.054,17.789 ; 50.546,20.329 51.054,20.329 ; 50.546,22.869 51.054,22.869 ; 50.546,25.409 51.054,25.409 ; 50.546,27.949 51.054,27.949 ; 50.546,35.569 51.054,35.569 ; 50.546,38.109 51.054,38.109 ; 50.546,40.649 51.054,40.649 ; 50.546,43.189 51.054,43.189 ; 50.546,45.729 51.054,45.729 ; 50.546,48.269 51.054,48.269 ; 50.546,50.809 51.054,50.809 ; 55.728,7.629 56.134,7.629 ; 55.728,10.169 56.134,10.169 ; 55.728,12.709 56.134,12.709 ; 55.728,15.249 56.134,15.249 ; 55.728,17.789 56.134,17.789 ; 55.728,20.329 56.134,20.329 ; 55.728,22.869 56.134,22.869 ; 55.728,25.409 56.134,25.409 ; 55.738,52.31 56.452,51.597 ; 55.75,29.459 56.464,28.745 ; 55.75,32.009 56.464,31.295 ; 55.75,34.509 56.464,33.795 ; 55.75,37.059 56.464,36.345 ; 55.75,39.609 56.464,38.895 ; 55.75,42.159 56.464,41.445 ; 55.75,44.709 56.464,43.995 ; 55.75,47.209 56.464,46.495 ; 55.75,49.759 56.464,49.045
  text "11" at 55.225,53.759 h1.52
  text "t" at 32.051,53.743 h4
  text "p" at 28.751,53.343 h4
  text "c" at 37.451,53.343 h4
  text "0" at 4.14,52.034 h1.52
  text "1" at 6.68,52.034 h1.52
  text "2" at 9.22,52.034 h1.52
  text "3" at 11.76,52.034 h1.52
  text "4" at 14.3,52.034 h1.52
  text "5" at 16.84,52.034 h1.52
  text "6" at 42.24,52.034 h1.52
  text "7" at 44.78,52.034 h1.52
  text "8" at 47.32,52.034 h1.52
  text "9" at 49.86,52.034 h1.52
  text "10" at 52.7,52.034 h1.52
  text "12" at 57.825,52.034 h1.52
  text "SCL - PA15" at 38.781,50.962 h1.52
  text "R" at 17.675,50.539 h1.52 r270
  text "R" at 39.6,50.414 h1.52 r270
  text "SDA - PA14" at 38.781,49.719 h1.52
  text "AREF" at 38.781,48.382 h1.52
  text "Q" at 17.675,47.999 h1.52 r270
  text "Q" at 39.6,47.874 h1.52 r270
  text "GND" at 38.781,47.045 h1.52
  text "SCK - PA09" at 38.781,45.946 h1.52
  text "P" at 17.675,45.459 h1.52 r270
  text "P" at 39.6,45.334 h1.52 r270
  text "MISO - PA24" at 38.781,44.262 h1.52
  text "MOSI - PA22" at 38.781,43.075 h1.52
  text "O" at 17.675,42.919 h1.52 r270
  text "O" at 39.6,42.794 h1.52 r270
  text "SS - PA23" at 38.781,41.917 h1.52
  text "N" at 17.675,40.379 h1.52 r270
  text "N" at 39.6,40.254 h1.52 r270
  text "M" at 17.675,37.839 h1.52 r270
  text "M" at 39.6,37.714 h1.52 r270
  text "L" at 17.675,35.299 h1.52 r270
  text "L" at 39.6,35.174 h1.52 r270
  text "PA22" at 53,33.909 h1.1
  text "K" at 17.675,32.759 h1.52 r270
  text "PA23" at 37.68,32.703 h1.52
  text "K" at 41.021,32.521 h1.52
  text "J" at 17.675,30.219 h1.52 r270
  text "PA24" at 37.716,30.151 h1.52
  text "J" at 41.021,29.981 h1.52
  text "PA9" at 52.95,28.859 h1.1
  text "I" at 17.675,27.679 h1.52 r270
  text "I" at 39.6,27.554 h1.52 r270
  text "h" at 38.75,26 h5.5
  text "H" at 17.675,25.139 h1.52 r270
  text "H" at 39.6,25.014 h1.52 r270
  text "G" at 17.675,22.599 h1.52 r270
  text "G" at 39.6,22.474 h1.52 r270
  text "F" at 17.675,20.059 h1.52 r270
  text "F" at 39.6,19.934 h1.52 r270
  text "E" at 17.675,17.519 h1.52 r270
  text "Atmel Corp © 2014" at 37.055,17.482 h2
  text "E" at 39.6,17.394 h1.52 r270
  text "D" at 17.675,14.979 h1.52 r270
  text "D" at 39.6,14.854 h1.52 r270
  text "C" at 17.675,12.439 h1.52 r270
  text "C" at 39.6,12.314 h1.52 r270
  text "ANALOG" at 1.192,11.363 h1.52 r270
  text "A08-2178 Rev 2" at 35.568,10.934 h2
  text "B" at 17.675,9.899 h1.52 r270
  text "B" at 39.6,9.774 h1.52 r270
  text "TX" at 59.778,9.725 h1.52
  text "A" at 17.675,7.359 h1.52 r270
  text "A" at 39.6,7.234 h1.52 r270
  text "RX" at 59.778,7.125 h1.52
  text "GND" at 20.835,4.644 h1.52
  text "GND" at 56,4.418 h1.52
  text "VCC" at 20.694,2.194 h1.52
  text "VCC" at 53.958,0.867 h1.52 r270
Mechanical 1:
  lines w0.1: 0,1.009 ccw(c1,1.009) 1,0.009 59,0.009 ccw(c59,1.009) 60,1.009 60,59.009 ccw(c59,59.009) 59,60.009 37,60.009 cw(c37,61.009) 36,61.009 36,74.009 ccw(c35,74.009) 35,75.009 25,75.009 ccw(c25,74.009) 24,74.009 24,61.009 cw(c23,61.009) 23,60.009 1,60.009 ccw(c1,59.009) 0,59.009 0,13.259 0,1.009
Mechanical 4:
  text "Mechanical Dimensions" at 11.008,85.39 h5
Mechanical 16:
  lines w0.127: -159,-66.906 -153.92,-66.906 ; -159,3.754 -153.92,3.754 ; -159,74.239 -153.92,74.239 ; -109.724,-137.391 -109.724,-132.311 ; -109.724,139.469 -109.724,144.549 ; -65.7,139.469 -65.7,144.549 ; -60.575,-137.391 -60.575,-132.311 ; -16.525,139.469 -16.525,144.549 ; -11.426,-137.391 -11.426,-132.311 ; 37.85,-137.391 37.85,-132.311 ; 37.85,139.469 37.85,144.549 ; 86.999,-137.391 86.999,-132.311 ; 86.999,139.469 86.999,144.549 ; 115.32,-124.691 229.62,-124.691 ; 115.32,-117.071 229.62,-117.071 ; 115.32,-109.451 153.42,-109.451 ; 136.148,-137.391 136.148,-132.311 ; 136.148,139.469 136.148,144.549 ; 153.42,-132.311 153.42,-117.071 153.42,-101.831 ; 185.424,-137.391 185.424,-132.311 ; 185.424,139.469 185.424,144.549 ; 206.76,-132.311 206.76,-117.071 ; 229.62,-66.906 234.7,-66.906 ; 229.62,3.709 234.7,3.709 ; 229.62,74.194 234.7,74.194 ; 115.32,-132.311 115.32,-101.831 ; 115.32,-132.311 229.62,-132.311 ; 115.32,-132.311 79.76,-132.311 79.76,-101.831 115.32,-101.831 ; 115.32,-101.831 153.42,-101.831 ; 153.42,-101.831 229.62,-101.831 229.62,-132.311 ; 229.62,-132.311 229.62,139.469 -153.92,139.469 -153.92,-132.311 229.62,-132.311 ; -159,-137.391 234.7,-137.391 234.7,144.549 -159,144.549 -159,-137.391
  text "1" at -134.963,141.12 h0.67
  text "4" at 12.628,141.12 h0.67
  text "5" at 61.904,141.12 h0.67
  text "6" at 110.926,141.12 h0.67
  text "7" at 160.456,141.12 h0.67
  text "8" at 209.478,141.12 h0.67
  text "2" at -88.474,140.984 h0.67
  text "3" at -41.924,140.834 h0.67
  text "A" at -157.095,107.309 h0.67
  text "A" at 231.525,107.264 h0.67
  text "B" at 231.605,39.209 h0.67
  text "B" at -157.095,36.697 h0.67
  text "C" at -157.188,-31.479 h0.67
  text "C" at 231.975,-37.091 h0.67
  text "D" at -157.095,-104.194 h0.67
  text "D" at 231.525,-104.194 h0.67
  text "ENGINEER:" at 116.59,-104.371 h0.67
  text "TITLE:" at 154.69,-104.371 h0.67
  text "PCB DESIGNER:" at 116.59,-111.864 h0.67
  text "B" at 82.525,-116.641 h20
  text "DATE:" at 116.59,-119.611 h0.67
  text "PART NO.:" at 154.69,-119.611 h0.67
  text "REV:" at 208.03,-119.611 h0.67
  text "ATMEL NORWAY" at 82.575,-120.241 h0.67
  text "Vestre Rosten 79" at 82.545,-122.319 h0.67
  text ".PRINT_DATE" at 116.7,-123.491 h0.67
  text "N-7075 Tiller" at 82.545,-125.621 h0.67
  text "FILE NAME:" at 116.59,-127.231 h0.67
  text "DWG NO:" at 154.69,-127.231 h0.67
  text "SCALE:" at 208.03,-127.231 h0.67
  text ".PCB_FILE_NAME_NO_PATH" at 117.86,-130.279 h0.67
  text "2" at -85.34,-135.679 h0.67
  text "3" at -35.81,-135.679 h0.67
  text "4" at 13.212,-135.679 h0.67
  text "5" at 61.904,-135.679 h0.67
  text "6" at 110.926,-135.679 h0.67
  text "7" at 160.456,-135.679 h0.67
  text "8" at 209.478,-135.679 h0.67

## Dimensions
60,59.009 to 36,61.009 on Mechanical 4
0,0.009 to 57.65,57.659 on Mechanical 4
0,0.009 to 2.35,57.659 on Mechanical 4
2.35,57.659 to 0,0.009 on Mechanical 4
2.35,2.359 to 0,1.009 on Mechanical 4
0,0.009 to 60,1.009 on Mechanical 4
60,0.009 to 59,60.009 on Mechanical 4
24,61.009 to 0,59.009 on Mechanical 4
36,74.009 to 24,74.009 on Mechanical 4
59,60.009 to 35,75.009 on Mechanical 4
